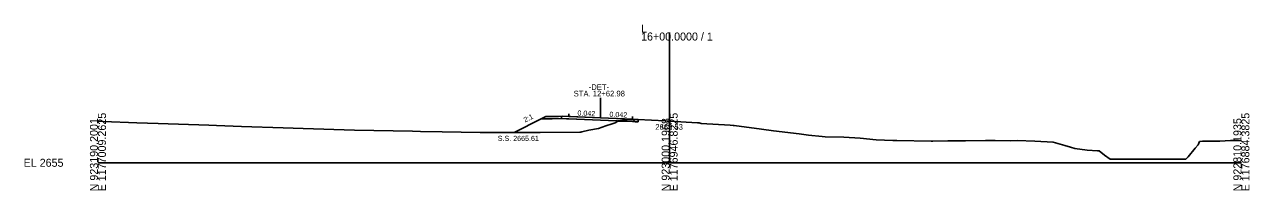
# Model space of a CAD drawing. Extents: x -26 to 1403, y -10 to 9563.
# Drawn here: x -25.7 to 402.8, y 5990.3 to 6048.3 of the extents above; entities that cross this region are included whole.
import ezdxf

# ---------------------------------------------------------------- set-up
doc = ezdxf.new("R2010")
doc.units = 0
for name, color, linetype in [('Exist Cross Section Cell', 7, 'Continuous'), ('Exist XS Center Line Elevation Label', 7, 'Continuous'), ('Exist XS Ground Line', 7, 'Continuous'), ('Prop XS Dump Level', 7, 'Continuous'), ('Prop XS Earthwork Shape', 7, 'Continuous'), ('Prop XS EOT Tick Mark', 7, 'Continuous'), ('Prop XS Finish Grade', 7, 'Continuous'), ('Prop XS Finish Grade Earthwork', 7, 'Continuous'), ('Prop XS Finish Grade Pavement', 7, 'Continuous'), ('Prop XS Pvmt Edge Slope', 7, 'Continuous'), ('Prop XS SE Text', 7, 'Continuous'), ('Prop XS Shoulder Borrow Shape', 7, 'Continuous'), ('Prop XS Side Slope Text', 7, 'Continuous'), ('Prop XS SS Elevation Text', 7, 'Continuous'), ('Prop XS Subgrade Earthwork', 7, 'Continuous'), ('Prop XS Vertical Lines', 7, 'Continuous')]:
    doc.layers.add(name, color=color, linetype=linetype)

msp = doc.modelspace()

# ---------------------------------------------------------------- linework, layer by layer
at = {"layer": 'Exist Cross Section Cell'}
for p, q in [((200, 6000), (200, 6045.54)), ((0, 6000), (200, 6000)), ((200, 6000), (400, 6000))]:
    msp.add_line(p, q, dxfattribs=at)
at = {"layer": 'Exist XS Ground Line'}
for p, q in [((0, 6014.5), (1.87, 6014.41)), ((1.87, 6014.41), (13.55, 6013.99)), ((13.55, 6013.99), (21.03, 6013.72)), ((21.03, 6013.72), (38.82, 6013.09)), ((38.82, 6013.09), (41.44, 6013)), ((41.44, 6013), (50.2, 6012.73)), ((50.2, 6012.73), (64.77, 6012.25)), ((175.09, 6011.94), (177.66, 6012.89)), ((177.66, 6012.89), (179.85, 6013.57)), ((179.85, 6013.57), (180.9, 6014.02)), ((180.9, 6014.02), (182.01, 6014.66)), ((182.01, 6014.66), (183.5, 6014.9)), ((183.5, 6014.9), (186.81, 6015.18)), ((186.81, 6015.18), (188.92, 6015.1)), ((188.92, 6015.1), (198.43, 6014.62)), ((198.43, 6014.62), (199.11, 6014.58)), ((199.11, 6014.58), (200, 6014.53)), ((200, 6014.53), (209.68, 6013.96)), ((209.68, 6013.96), (210.35, 6013.92)), ((210.35, 6013.92), (211.06, 6013.78)), ((211.06, 6013.78), (221.15, 6013.11)), ((221.15, 6013.11), (222.24, 6013.03)), ((222.24, 6013.03), (222.58, 6013.01)), ((222.58, 6013.01), (232.11, 6011.8)), ((64.77, 6012.25), (71.82, 6012.03)), ((71.82, 6012.03), (89.7, 6011.42)), ((89.7, 6011.42), (110.03, 6011.04)), ((110.03, 6011.04), (112.81, 6010.99)), ((112.81, 6010.99), (120.43, 6010.86)), ((120.43, 6010.86), (133.71, 6010.64)), ((133.71, 6010.64), (143.47, 6010.63)), ((143.47, 6010.63), (154.74, 6010.56)), ((154.74, 6010.56), (168.58, 6010.69)), ((168.58, 6010.69), (168.94, 6010.71)), ((168.94, 6010.71), (169.27, 6010.78)), ((169.27, 6010.78), (171.68, 6011.39)), ((171.68, 6011.39), (175.09, 6011.94)), ((232.11, 6011.8), (236.36, 6011.22)), ((236.36, 6011.22), (245.36, 6010.17)), ((245.36, 6010.17), (248.51, 6009.6)), ((248.51, 6009.6), (253.32, 6009.21)), ((253.32, 6009.21), (254.37, 6009.07)), ((254.37, 6009.07), (260.96, 6008.94)), ((260.96, 6008.94), (266.62, 6008.58)), ((266.62, 6008.58), (272.25, 6008.03)), ((272.25, 6008.03), (275.15, 6007.88)), ((275.15, 6007.88), (278.09, 6007.82)), ((278.09, 6007.82), (279.43, 6007.78)), ((279.43, 6007.78), (291.46, 6007.58)), ((291.46, 6007.58), (292.12, 6007.61)), ((292.12, 6007.61), (297.35, 6007.63)), ((297.35, 6007.63), (303.46, 6007.66)), ((303.46, 6007.66), (310.49, 6007.82)), ((310.49, 6007.82), (313.85, 6007.75)), ((313.85, 6007.75), (319.24, 6007.68)), ((319.24, 6007.68), (321.52, 6007.73)), ((321.52, 6007.73), (327.69, 6007.57)), ((327.69, 6007.57), (334.1, 6007.25)), ((334.1, 6007.25), (338.23, 6006)), ((338.23, 6006), (340.26, 6005.48)), ((340.26, 6005.48), (341.68, 6005.03)), ((341.68, 6005.03), (346.09, 6004.38)), ((346.09, 6004.38), (349.71, 6004.21)), ((349.71, 6004.21), (350.29, 6004.16)), ((350.29, 6004.16), (352.12, 6002.63)), ((381.38, 6002.08), (383.88, 6005.09)), ((383.88, 6005.09), (384.84, 6006.23)), ((384.84, 6006.23), (385.39, 6007.41)), ((385.39, 6007.41), (386.34, 6007.5)), ((386.34, 6007.5), (392.42, 6007.59)), ((392.42, 6007.59), (396.19, 6007.82)), ((396.19, 6007.82), (399.03, 6007.73)), ((399.03, 6007.73), (400, 6007.72)), ((352.12, 6002.63), (354.14, 6001.23)), ((354.14, 6001.23), (359.38, 6001.23)), ((359.38, 6001.23), (361.61, 6001.23)), ((361.61, 6001.23), (366.82, 6001.22)), ((366.82, 6001.22), (371.95, 6001.22)), ((371.95, 6001.22), (380.57, 6001.22)), ((380.57, 6001.22), (381.38, 6002.08))]:
    msp.add_line(p, q, dxfattribs=at)
at = {"layer": 'Prop XS Dump Level'}
for p, q in [((162.67, 6016.24), (175.86, 6015.68)), ((175.86, 6015.68), (164.67, 6016.15)), ((187.05, 6015.22), (175.86, 6015.68)), ((175.86, 6015.68), (187.05, 6015.22))]:
    msp.add_line(p, q, dxfattribs=at)
at = {"layer": 'Prop XS Earthwork Shape'}
for p, q in [((155.04, 6015.31), (145.65, 6010.62)), ((158.88, 6015.38), (155.04, 6015.31)), ((161.87, 6015.44), (158.88, 6015.38)), ((175.09, 6011.94), (177.66, 6012.89)), ((181.5, 6014.61), (175.86, 6014.85)), ((177.66, 6012.89), (179.85, 6013.57)), ((179.85, 6013.57), (180.9, 6014.02)), ((180.9, 6014.02), (181.9, 6014.59)), ((181.49, 6014.61), (181.5, 6014.61)), ((181.9, 6014.59), (181.49, 6014.61)), ((181.91, 6014.6), (182.01, 6014.66)), ((187.05, 6014.38), (181.91, 6014.6)), ((182.01, 6014.66), (183.5, 6014.9)), ((183.5, 6014.9), (186.81, 6015.18)), ((186.81, 6015.18), (188.92, 6015.1)), ((187.92, 6014.35), (187.05, 6014.38)), ((189.01, 6014.3), (187.92, 6014.35)), ((189.01, 6015.09), (189.01, 6014.3)), ((145.65, 6010.62), (154.74, 6010.56)), ((154.74, 6010.56), (168.58, 6010.69)), ((168.58, 6010.69), (168.94, 6010.71)), ((168.94, 6010.71), (169.27, 6010.78)), ((169.27, 6010.78), (171.68, 6011.39)), ((171.68, 6011.39), (175.09, 6011.94))]:
    msp.add_line(p, q, dxfattribs=at)
msp.add_lwpolyline([(175.86, 6014.85), (164.67, 6015.32), (163.87, 6015.35), (161.87, 6015.44)], dxfattribs=at)
at = {"layer": 'Prop XS EOT Tick Mark'}
for p, q in [((164.67, 6016.15), (164.67, 6017.15)), ((187.05, 6015.22), (187.05, 6016.22))]:
    msp.add_line(p, q, dxfattribs=at)
at = {"layer": 'Prop XS Finish Grade'}
msp.add_line((162.67, 6016.24), (161.1, 6016.21), dxfattribs=at)
at = {"layer": 'Prop XS Finish Grade Earthwork'}
for p, q in [((155.04, 6015.31), (145.65, 6010.62)), ((156.67, 6016.13), (155.04, 6015.31)), ((161.1, 6016.21), (156.67, 6016.13))]:
    msp.add_line(p, q, dxfattribs=at)
at = {"layer": 'Prop XS Finish Grade Pavement'}
for p, q in [((162.67, 6016.24), (175.86, 6015.68)), ((175.86, 6015.68), (187.05, 6015.22)), ((187.05, 6015.22), (189.01, 6015.13))]:
    msp.add_line(p, q, dxfattribs=at)
at = {"layer": 'Prop XS Pvmt Edge Slope'}
for p, q in [((162.67, 6016.24), (161.87, 6015.44)), ((187.05, 6015.22), (187.92, 6014.35))]:
    msp.add_line(p, q, dxfattribs=at)
at = {"layer": 'Prop XS Shoulder Borrow Shape'}
for p, q in [((156.67, 6016.13), (155.04, 6015.31)), ((155.04, 6015.31), (158.88, 6015.38)), ((161.1, 6016.21), (156.67, 6016.13)), ((158.88, 6015.38), (161.87, 6015.44)), ((162.67, 6016.24), (161.1, 6016.21)), ((161.87, 6015.44), (162.67, 6016.24))]:
    msp.add_line(p, q, dxfattribs=at)
at = {"layer": 'Prop XS Subgrade Earthwork'}
for p, q in [((158.88, 6015.38), (155.04, 6015.31)), ((161.87, 6015.44), (158.88, 6015.38)), ((175.86, 6014.85), (161.87, 6015.44)), ((164.67, 6015.32), (163.87, 6015.35)), ((187.05, 6014.38), (175.86, 6014.85)), ((187.05, 6014.38), (187.92, 6014.35)), ((187.92, 6014.35), (189.01, 6014.3)), ((189.01, 6014.3), (189.01, 6015.09))]:
    msp.add_line(p, q, dxfattribs=at)
at = {"layer": 'Prop XS Vertical Lines'}
msp.add_line((175.86, 6015.68), (175.86, 6022.68), dxfattribs=at)

# ---------------------------------------------------------------- texts
at = {"layer": 'Exist Cross Section Cell'}
for s, p in [('L', (190, 6045.54)), ('16+00.0000 / 1', (190, 6042.74)), ('EL 2655', (-26, 5998.6))]:
    msp.add_text(s, height=2.8, dxfattribs=at).set_placement(p)
for s, p in [('E 1177009.2625', (2.8, 5990)), ('E 1176946.8225', (202.8, 5990)), ('E 1176884.3825', (402.8, 5990)), ('N 923190.2001', (0, 5990)), ('N 923000.1968', (200, 5990)), ('N 922810.1935', (400, 5990))]:
    msp.add_text(s, height=2.8, rotation=90, dxfattribs=at).set_placement(p)
at = {"layer": 'Exist XS Center Line Elevation Label'}
msp.add_text('2669.53', height=2, dxfattribs=at).set_placement((194.96, 6011.53))
at = {"layer": 'Prop XS Dump Level'}
msp.add_text('Case1', height=0.04, dxfattribs=at).set_placement((156.67, 6015.97))
at = {"layer": 'Prop XS SE Text'}
for p in [(167.72, 6016.52), (178.91, 6016.06)]:
    msp.add_text('0.042', height=1.8, rotation=357.6059, dxfattribs=at).set_placement(p)
at = {"layer": 'Prop XS Side Slope Text'}
msp.add_text('2:1', height=1.8, rotation=26.5651, dxfattribs=at).set_placement((149.41, 6014.05))
at = {"layer": 'Prop XS SS Elevation Text'}
msp.add_text('S.S. 2665.61', height=1.8, dxfattribs=at).set_placement((139.87, 6007.62))
at = {"layer": 'Prop XS Vertical Lines'}
for s, p in [('STA. 12+62.98', (166.43, 6023.19)), ('-DET-', (171.69, 6025.44))]:
    msp.add_text(s, height=2, dxfattribs=at).set_placement(p)

doc.saveas('drawing.dxf')
